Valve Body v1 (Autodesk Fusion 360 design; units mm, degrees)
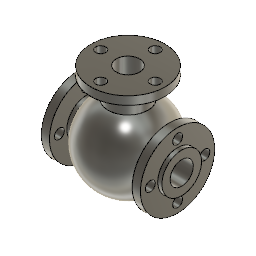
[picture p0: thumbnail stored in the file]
sketch "Sketch1" plane through (0, 0, 0) normal (0, 1, 0) x axis (1, 0, 0)
  line L1 (0, 0) -> (77.5417, 0)
  line L2 (0, -65.0755) -> (0, 0)
  line L3 (65, -24) -> (65, -14)
  line L4 (60, -24) -> (65, -24)
  line L5 (60, -45) -> (60, -24)
  line L6 (50, -45) -> (60, -45)
  line L7 (50, -24) -> (50, -45)
  line L8 (45, -24) -> (50, -24)
  line L9 (65, -14) -> (38.5357, -14)
  line L10 (-45, -24) -> (-50, -24)
  line L11 (-65, -14) -> (-38.5357, -14)
  line L12 (-65, -24) -> (-65, -14)
  line L13 (-60, -24) -> (-65, -24)
  line L14 (-60, -45) -> (-60, -24)
  line L15 (-50, -45) -> (-60, -45)
  line L16 (-50, -24) -> (-50, -45)
  arc A1 centre (0, 0) radius 51 clockwise from (45, -24) to (-45, -24)
  arc A2 centre (0, 0) radius 41 clockwise from (38.5357, -14) to (-38.5357, -14)
  point P1 (0, 0)
  point P2 (0, 0)
  point P3 (0, 0)
  point P5 (0, 0)
  point P7 (65, -14)
  point P18 (-65, -14)
  point P8 (65, -24)
  point P19 (-65, -24)
  point P9 (60, -24)
  point P20 (-60, -24)
  point P10 (60, -45)
  point P21 (-60, -45)
  point P11 (50, -45)
  point P22 (-50, -45)
  point P12 (50, -24)
  point P15 (-50, -24)
  point P13 (45, -24)
  point P16 (-45, -24)
  point P14 (38.5357, -14)
  point P17 (-38.5357, -14)
  coincident P1 P2
  concentric A1 A2
  coincident P3 P5
  horizontal L1
  perpendicular L1 L2
  perpendicular L3 L4
  perpendicular L4 L5
  perpendicular L5 L6
  perpendicular L6 L7
  perpendicular L7 L8
  collinear L4 L8
  symmetric L2 P7 P18
  symmetric L2 P8 P19
  symmetric L2 P9 P20
  symmetric L2 P10 P21
  symmetric L2 P11 P22
  symmetric L2 P12 P15
  symmetric L2 P13 P16
  symmetric L2 P14 P17
  dimension "d2" radius A1 = 51
  dimension "d4" radius A2 = 41
  dimension "d5" = 28
  dimension "d6" = 48
  dimension "d7" = 90
  dimension "d8" distance P8 P9 = 5
  dimension "d10" distance L3 L12 = 130
  dimension "d11" distance P21 P22 = 10
revolve "Revolve1" sketch "Sketch1" AlongAngle 360
work_plane "WorkPlane2" AlongDistance 70
sketch "Sketch3" plane through (0, 0, 70) normal (0, 0, 1) x axis (1, 0, 0)
  circle C1 centre (0, 0) radius 24
  point P1 (0, 0)
  point P2 (0, 0)
  coincident P1 P2
  dimension "d15" diameter C1 = 48
extrude "Extrude2" add sketch "Sketch3" to an object
sketch "Sketch6" plane through (0, 0, 70) normal (0, 0, 1) x axis (-1, 0, 0)
  circle C1 centre (0, 0) radius 24
  circle C2 centre (0, 0) radius 45
  point P1 (0, 0)
  point P3 (0, 0)
  coincident P1 P3
  dimension "d21" diameter C2 = 90
extrude "Extrude3" add sketch "Sketch6" along normal blind 10
sketch "Sketch9" plane through (0, 0, 80) normal (0, 0, 1) x axis (-1, 0, 0)
  circle C1 centre (0, 0) radius 45
  circle C2 centre (0, 0) radius 14
  point P1 (0, 0)
  point P3 (0, 0)
  coincident P1 P3
  dimension "d32" diameter C2 = 28
extrude "Extrude7" cut sketch "Sketch9" profile of C2 to an object
sketch "Sketch10" plane through (60, 0, 0) normal (1, 0, 0) x axis (0, 1, 0)
  circle C1 centre (0, 0) radius 24
  circle C2 centre (0, 0) radius 45
  circle C3 centre (0, 33) radius 6
  point P1 (0, 0)
  point P3 (0, 33)
  vertical P1 P3
  dimension "d35" diameter C3 = 12
  dimension "d36" distance P1 P3 = 33
extrude "Extrude8" cut sketch "Sketch10" profile of C3 against normal blind 10
circular_pattern "C-Pattern1" TotalAngle 360
mirror "Mirror2"
sketch "Sketch11" plane through (0, 0, 80) normal (0, 0, 1) x axis (-1, 0, 0)
  circle C1 centre (0, 0) radius 14
  circle C2 centre (0, 0) radius 45
  circle C3 centre (0, -33) radius 6
  point P1 (0, 0)
  point P3 (0, -33)
  vertical P1 P3
  dimension "d43" diameter C3 = 12
  dimension "d44" distance P1 P3 = 33
extrude "Extrude9" cut sketch "Sketch11" profile of C3 against normal blind 10
circular_pattern "C-Pattern2" TotalAngle 360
